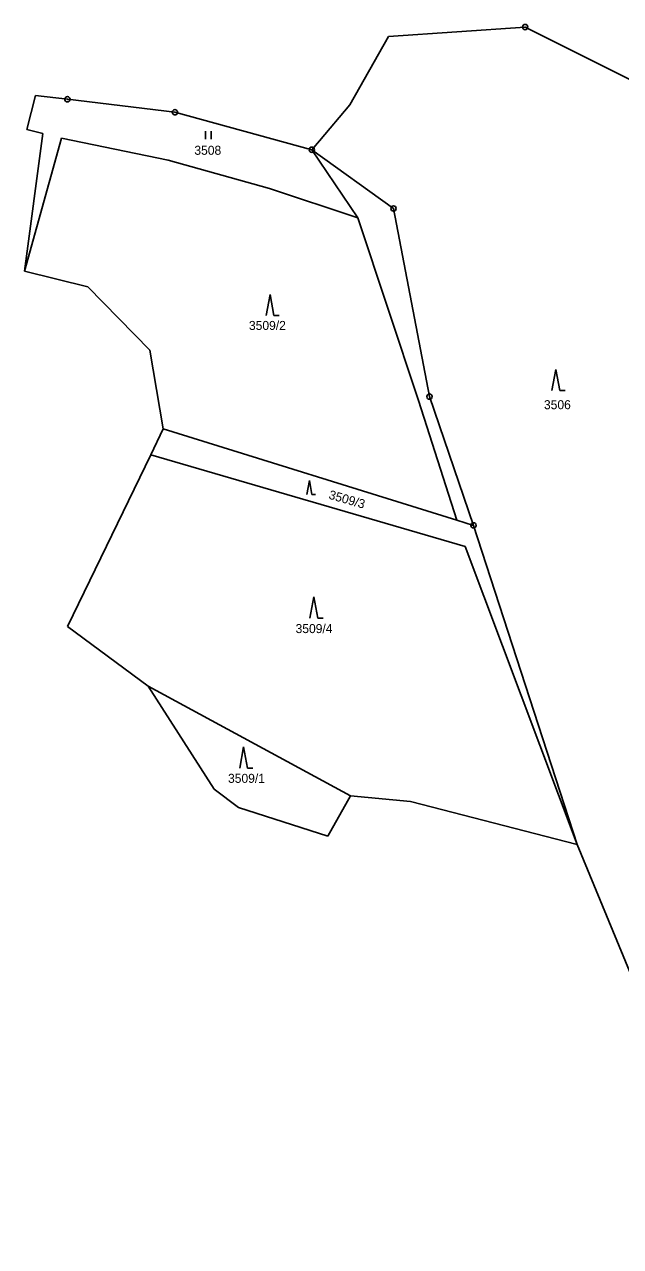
# Model space of a CAD drawing. Extents: x -593183 to -588034, y -1130415 to -1124994.
# Drawn here: x -593183.1 to -593070.9, y -1129185.2 to -1128954.8 of the extents above; entities that cross this region are included whole.
import ezdxf

# ---------------------------------------------------------------- set-up
doc = ezdxf.new("R2010")
doc.units = 0
for name, color, linetype in [('Vrstva 1', 7, 'Continuous'), ('Vrstva 13', 7, 'Continuous'), ('Vrstva 18', 7, 'Continuous'), ('Vrstva 24', 7, 'Continuous'), ('Vrstva 25', 7, 'Continuous'), ('Vrstva 4', 7, 'Continuous')]:
    doc.layers.add(name, color=color, linetype=linetype)

msp = doc.modelspace()

# ---------------------------------------------------------------- linework, layer by layer
at = {"layer": 'Vrstva 1'}
for p, q in [((-593183.12, -1129001.29), (-593176.14, -1128976.2)), ((-593176.14, -1128976.2), (-593156.06, -1128980.38)), ((-593129.01, -1128978.41), (-593113.63, -1128989.48)), ((-593156.06, -1128980.38), (-593136.96, -1128985.7)), ((-593136.96, -1128985.7), (-593120.34, -1128991.26)), ((-593113.63, -1128989.48), (-593106.85, -1129024.95)), ((-593120.34, -1128991.26), (-593108.93, -1129025.66)), ((-593108.93, -1129025.66), (-593101.72, -1129048.23)), ((-593106.85, -1129024.95), (-593098.57, -1129049.21)), ((-593157, -1129031.02), (-593101.72, -1129048.23)), ((-593159.31, -1129035.92), (-593100.13, -1129053.22)), ((-593101.72, -1129048.23), (-593098.57, -1129049.21)), ((-593098.57, -1129049.21), (-593079.05, -1129109.37)), ((-593100.13, -1129053.22), (-593079.05, -1129109.37)), ((-593159.85, -1129079.51), (-593121.75, -1129100.22))]:
    msp.add_line(p, q, dxfattribs=at)
at = {"layer": 'Vrstva 13'}
for p, q in [((-593114.6, -1128957.09), (-593088.84, -1128955.29)), ((-593065.2, -1128967.17), (-593088.84, -1128955.29)), ((-593121.85, -1128969.93), (-593114.6, -1128957.09)), ((-593182.66, -1128974.62), (-593181.05, -1128968.16)), ((-593181.05, -1128968.16), (-593175.04, -1128968.89)), ((-593175.04, -1128968.89), (-593154.79, -1128971.34)), ((-593154.79, -1128971.34), (-593129.01, -1128978.41)), ((-593127.58, -1128976.72), (-593121.85, -1128969.93)), ((-593179.67, -1128975.35), (-593183.12, -1129001.29)), ((-593182.66, -1128974.62), (-593179.67, -1128975.35)), ((-593129.01, -1128978.41), (-593127.58, -1128976.72)), ((-593183.12, -1129001.29), (-593171.18, -1129004.26)), ((-593171.18, -1129004.26), (-593159.53, -1129016.17)), ((-593159.53, -1129016.17), (-593157, -1129031.02)), ((-593159.31, -1129035.92), (-593157, -1129031.02)), ((-593175.02, -1129068.29), (-593159.31, -1129035.92)), ((-593175.02, -1129068.29), (-593159.85, -1129079.51)), ((-593159.85, -1129079.51), (-593147.4, -1129098.94)), ((-593147.4, -1129098.94), (-593142.83, -1129102.39)), ((-593126.02, -1129107.82), (-593121.75, -1129100.22)), ((-593121.75, -1129100.22), (-593110.41, -1129101.28)), ((-593142.83, -1129102.39), (-593126.02, -1129107.82)), ((-593110.41, -1129101.28), (-593079.05, -1129109.37)), ((-593079.05, -1129109.37), (-593047.84, -1129185.16))]:
    msp.add_line(p, q, dxfattribs=at)
at = {"layer": 'Vrstva 24'}
for centre, radius in [((-593088.84, -1128955.29), 0.5), ((-593088.84, -1128955.29), 0.0327), ((-593175.04, -1128968.89), 0.5), ((-593175.04, -1128968.89), 0.0327), ((-593154.79, -1128971.34), 0.5), ((-593154.79, -1128971.34), 0.0327), ((-593129.01, -1128978.41), 0.5), ((-593129.01, -1128978.41), 0.0327), ((-593113.63, -1128989.48), 0.5), ((-593113.63, -1128989.48), 0.0327), ((-593106.85, -1129024.95), 0.5), ((-593106.85, -1129024.95), 0.0327), ((-593098.57, -1129049.21), 0.5), ((-593098.57, -1129049.21), 0.0327)]:
    msp.add_circle(centre, radius, dxfattribs=at)
at = {"layer": 'Vrstva 25'}
for p, q in [((-593149.01, -1128974.9), (-593149.01, -1128976.4)), ((-593147.98, -1128976.4), (-593147.98, -1128974.9)), ((-593136.87, -1129005.67), (-593137.6, -1129009.67)), ((-593136.87, -1129005.67), (-593136.14, -1129009.67)), ((-593136.14, -1129009.67), (-593135.14, -1129009.67)), ((-593083.05, -1129019.82), (-593083.79, -1129023.82)), ((-593083.05, -1129019.82), (-593082.32, -1129023.82)), ((-593082.32, -1129023.82), (-593081.32, -1129023.82)), ((-593129.47, -1129040.73), (-593129.97, -1129043.41)), ((-593129.47, -1129040.73), (-593128.98, -1129043.41)), ((-593128.98, -1129043.41), (-593128.31, -1129043.41)), ((-593128.63, -1129062.7), (-593129.36, -1129066.7)), ((-593128.63, -1129062.7), (-593127.9, -1129066.7)), ((-593127.9, -1129066.7), (-593126.9, -1129066.7)), ((-593141.86, -1129090.96), (-593142.59, -1129094.96)), ((-593141.86, -1129090.96), (-593141.13, -1129094.96)), ((-593141.13, -1129094.96), (-593140.13, -1129094.96))]:
    msp.add_line(p, q, dxfattribs=at)
at = {"layer": 'Vrstva 4'}
msp.add_line((-593129.01, -1128978.41), (-593120.34, -1128991.26), dxfattribs=at)

# ---------------------------------------------------------------- texts
at = {"layer": 'Vrstva 18'}
for s, p in [('3508', (-593151.13, -1128979.36)), ('3509/2', (-593140.85, -1129012.38)), ('3506', (-593085.3, -1129027.32)), ('3509/4', (-593132.07, -1129069.52)), ('3509/1', (-593144.79, -1129097.75))]:
    msp.add_text(s, height=1.7, dxfattribs=at).set_placement(p)
msp.add_text('3509/3', height=1.7, rotation=343.9184, dxfattribs=at).set_placement((-593125.96, -1129044.16))

doc.saveas('drawing.dxf')
